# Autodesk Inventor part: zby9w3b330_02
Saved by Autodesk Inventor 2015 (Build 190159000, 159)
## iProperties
Created: 2019-08
Part Number: zby9w3b330_02
Checked By: TraceParts S.A.
Material: Générique
Catalog Web Link: www.traceparts.com
Document SubType Name: Modeling
Designer: TraceParts
Density: 1 g/cm^3
Appearance: Par défaut
Company: TraceParts S.A.
Author: TraceParts
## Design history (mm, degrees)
feature "zby9w3b330_02.ipt"
node "Solide1"
